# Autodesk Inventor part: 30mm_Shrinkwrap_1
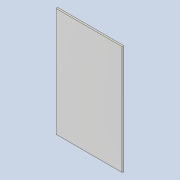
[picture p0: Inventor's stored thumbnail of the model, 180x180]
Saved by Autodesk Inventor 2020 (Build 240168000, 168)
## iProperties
Created: 2020-11
Part Number: 30mm_Shrinkwrap_1
Material: Generic
Document SubType Name: Sheet Metal
Designer: Yolande
Density: 1 g/cm^3
Sheet Metal Rule: Default
Appearance: Default
description: 0:0:Lambdaboard 30mm White Mineral
manufacturer: 0:0:Lambdaboard T/A Rigifoam
model: 0:0:
url: 0:0:www.lambdaboard.com
Author: Yolande
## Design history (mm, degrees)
derived "30mm.iam"
body "Solid1"
node "Lambdaboard 30mm Mineral White.ipt:1" dims "d0" = 10
other parameters: "Thickness" = 3.048, "KFactor" = 4.4, "BendRadius" = 3.048 (= Thickness), "BendReliefWidth" = 3.048 (= Thickness), "BendReliefDepth" = 1.524 (= 0.5 x Thickness), "CornerReliefSize" = 12.192 (= 4 x Thickness), "SeamGap" = 0.00508, "MinimumRemnant" = 6.096 (= 2 x Thickness), "TransitionRadius" = 3.048 (= BendRadius), "JacobiRadiusSize" = 3.048 (= Thickness), "GapSize" = 3.048 (= Thickness)
